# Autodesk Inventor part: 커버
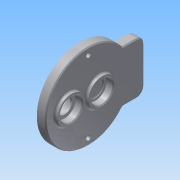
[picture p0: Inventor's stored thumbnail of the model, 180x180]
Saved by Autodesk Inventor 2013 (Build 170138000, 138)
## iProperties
Created: 2016-02
Part Number: 커버
Material: 알루미늄 6061
Document SubType Name: Modeling
Designer: mduedu
Density: 1 g/cm^3
Mass: 58.0254 g
Surface Area: 178.476 cm^2
Volume: 58.0254 cm^3
Author: mduedu
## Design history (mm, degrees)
sketch "스케치1"
  geometry: C1 r 43 at (0, 0); 1 further point
  constraints: 1 centre point, 1 coincident
  dimensions: "d0" = 86 diameter of C1
extrude "돌출1" new body sketch "스케치1" distance "d1" = 9; taper "d2" = 0 deg
sketch "스케치2"
  geometry: C1 r 14 at (0, 11); 1 further point
  constraints: 1 centre point, 1 vertical alignment
  dimensions: "d3" = 28 diameter of C1; "d6" = 11 distance of C1.centre point (0, 0)
extrude "돌출2" join sketch "스케치2" distance "d7" = 3; taper "d8" = 0 deg
sketch "스케치3"
  geometry: C1 r 14 at (0, -20); 1 further point
  constraints: 1 centre point, 1 vertical alignment
  dimensions: "d9" = 28 diameter of C1; "d10" = 20 distance of C1.centre point (0, 0)
extrude "돌출3" join sketch "스케치3" distance "d11" = 3; taper "d12" = 0 deg
hole "구멍1" diameter "d15" = 22; stored, may be unused: countersink angle "d19" = 90 deg, drill point angle "d21" = 0 deg; dims "d13" = 10, "d14" = 10, "d16" = 6, "d17" = 4, "d18" = 2, "d20" = 7
hole "구멍2" diameter "d24" = 18; stored, may be unused: countersink angle "d28" = 90 deg, drill point angle "d30" = 0 deg; dims "d22" = 10, "d23" = 10, "d25" = 6, "d26" = 4, "d27" = 2, "d29" = 1
hole "구멍3" diameter "d33" = 22; stored, may be unused: countersink angle "d37" = 90 deg, drill point angle "d39" = 0 deg; dims "d34" = 6, "d35" = 4, "d36" = 2, "d38" = 7, "d73" = 10, "d74" = 10
sketch "스케치7"
  geometry: L1 (-26, 34.249)-(26, 34.249); L2 (26, 34.249)-(26, 56); L3 (26, 56)-(-26, 56); L4 (-26, 56)-(-26, 34.249); A1 r 43 centre (0, 0) between (-26, 34.249) and (26, 34.249) reference; 1 further point
  constraints: 8 end point, 2 parallel, 2 point on circle, 1 horizontal, 1 perpendicular
  dimensions: "d95" = 52 distance of L2.end L3.end; "d97" = 56 distance from line of L3 point (0, 0)
extrude "돌출5" join sketch "스케치7" stored distance "d98" = 10; taper "d99" = 0 deg
sketch "스케치4"
  geometry: C1 r 14 at (0, -20) reference; C2 r 18 at (0, -20); 1 further point
  constraints: 1 centre point, 1 coincident
  dimensions: "d40" = 36 diameter of C2
extrude "돌출4" join sketch "스케치4" distance "d41" = 4; taper "d42" = 0 deg
hole "구멍4" diameter "d45" = 22; stored, may be unused: countersink angle "d49" = 90 deg, drill point angle "d51" = 0 deg; dims "d43" = 10, "d44" = 10, "d46" = 6, "d47" = 4, "d48" = 2, "d50" = 7
hole "구멍5" diameter "d54" = 15; stored, may be unused: countersink angle "d58" = 90 deg, drill point angle "d60" = 0 deg; dims "d52" = 10, "d53" = 10, "d55" = 6, "d56" = 4, "d57" = 2, "d59" = 7
fillet "모깎기1" dims "d61" = 0.3
fillet "모깎기2" dims "d62" = 2
chamfer "모따기1" distance "d63" = 1; stored, may be unused: second distance "d64" = 2, angle "d65" = 45 deg
fillet "모깎기6" dims "d88" = 2
sketch "스케치5" dims "d67" = 72
  geometry: 4 further points
  constraints: 2 horizontal alignment, 1 coincident, 5 other
  dimensions: "d71" = 360 deg dimension on point (0, 0) point (-36, 0) (derived)
fillet "모깎기4" dims "d75" = 2
sketch "스케치6"
  geometry: 2 further points
hole "구멍6" sketch "스케치6" at (36, 0), (-36, 0) diameter "d76" = 4.5; stored, may be unused: countersink angle "d80" = 90 deg, drill point angle "d82" = 0 deg; dims "d77" = 6, "d78" = 8, "d79" = 4.6, "d81" = 8
fillet "모깎기7" dims "d100" = 8, "d101" = 2
chamfer "모따기2" distance "d90" = 1; stored, may be unused: second distance "d91" = 2, angle "d92" = 45 deg
node "솔리드1"
node "절단 모서리 투영1"
